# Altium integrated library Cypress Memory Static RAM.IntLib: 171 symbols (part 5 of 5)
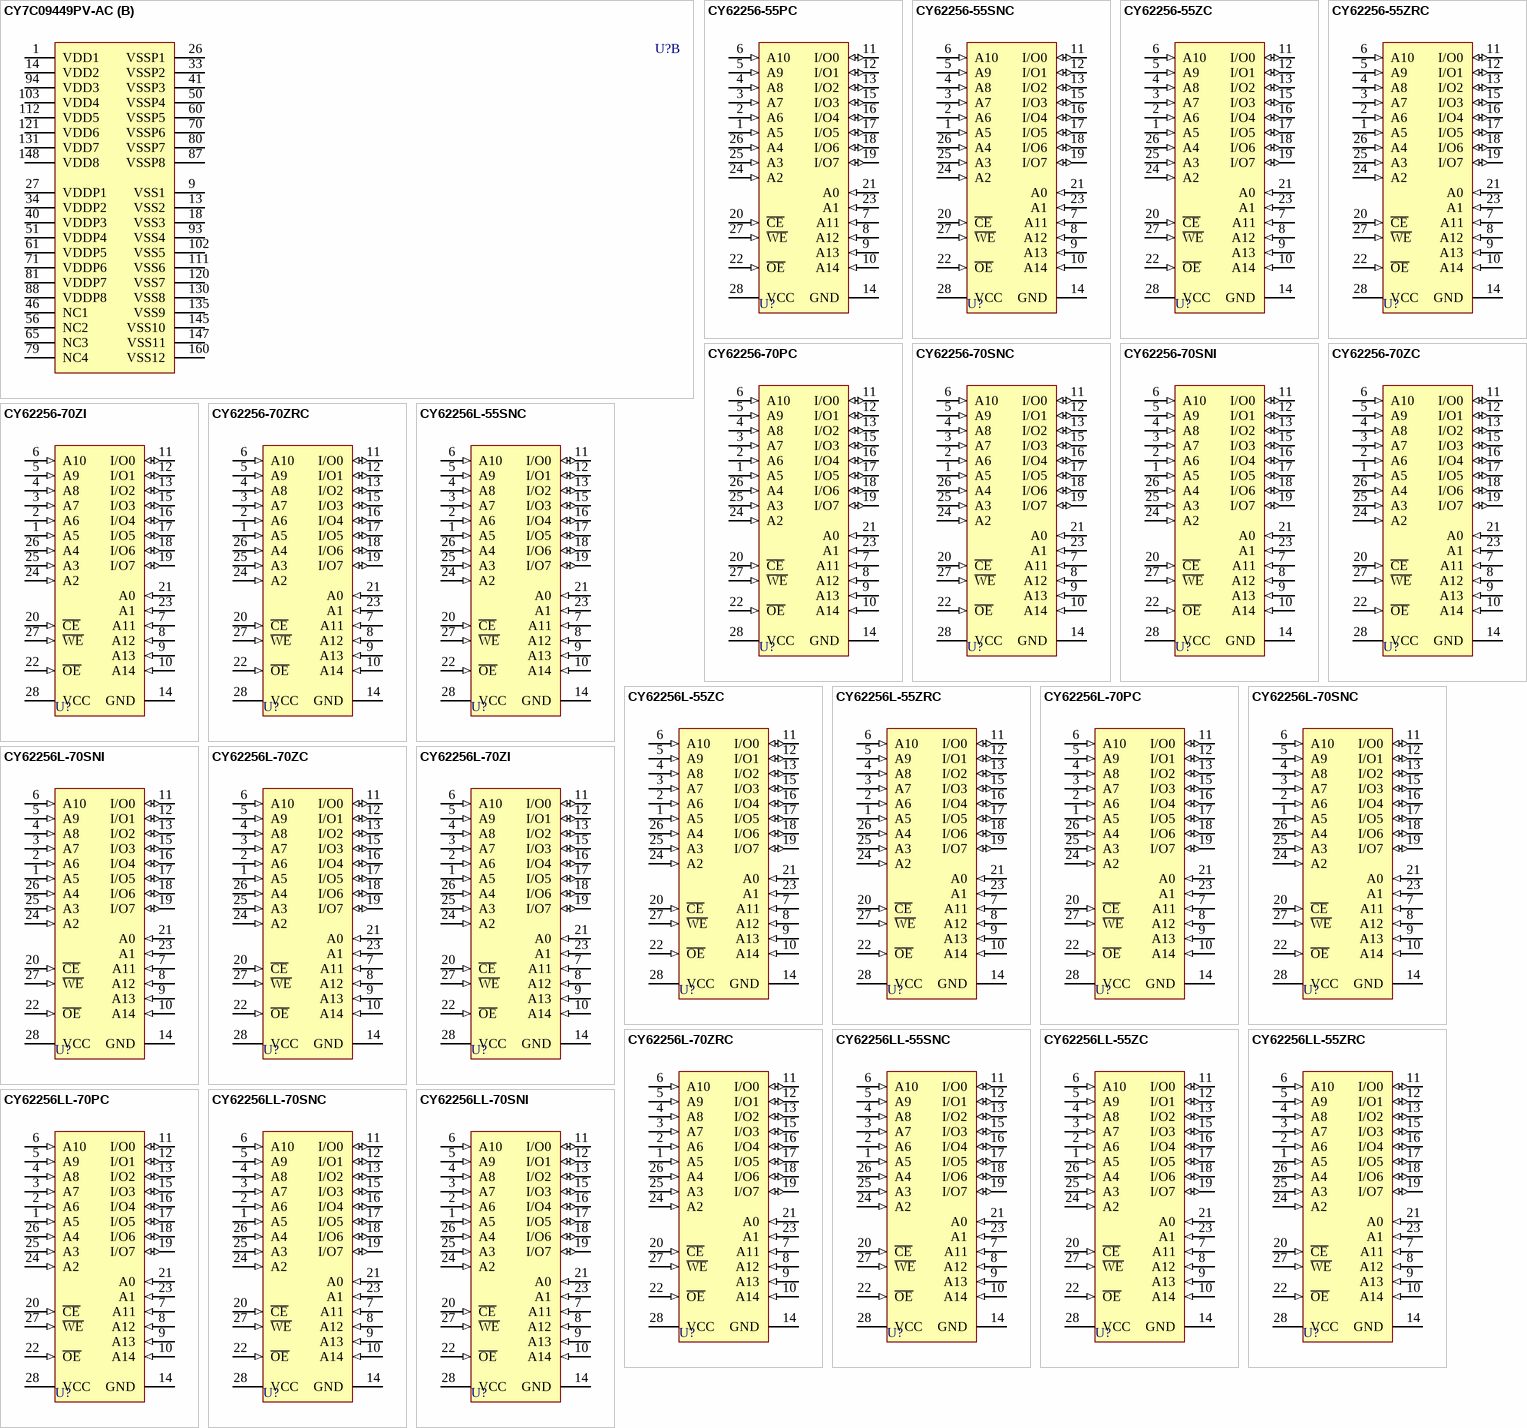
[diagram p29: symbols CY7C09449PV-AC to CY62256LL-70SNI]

## CY7C09449PV-AC
designator U?
128K Bit Dual-Port SRAM with PCI Bus Controller
footprint TQFP160_N (Thin QFP, 160-Leads, Body 24x24mm, Pitch 0.5mm, IPC Medium Density)
footprint TQFP160_L (Thin QFP, 160-Leads, Body 24x24mm, Pitch 0.5mm, IPC High Density)
footprint TQFP160_M (Thin QFP, 160-Leads, Body 24x24mm, Pitch 0.5mm, IPC Low Density)
3D model CY7C09449PV-TQFP160 (160-Pin Thin Quad Flat Pack 0.5 mm Pitch)
part A pins: 2 ADR[8] (in), 3 ADR[7] (in), 4 ADR[6] (in), 5 ADR[5] (in), 6 ADR[4] (in), 7 ADR[3] (in), 8 ADR[2] (in), 10 ALE (in), 11 ~{IRQ_IN} (in), 12 ~{IRQ_OUT} (hiz), 15 RSTOUTD (out), 16 ~{RSTOUTD} (out), 17 ~{RSTOUT} (out), 19 ~{SELECT} (in), 20 SDA (oc), 21 SCL (oc), 22 TEST_MODE (in), 23 ~{INTA} (oc), 24 ~{RST} (in), 25 CLK (in), 28 ~{GNT} (hiz), 29 ~{REQ} (hiz), 30 AD[31] (hiz), 31 AD[30] (hiz), 32 AD[29] (hiz), 35 AD[28] (hiz), 36 AD[27] (hiz), 37 AD[26] (hiz), 38 AD[25] (hiz), 39 AD[24] (hiz), 42 C/~{BE}[3] (hiz), 43 IDSEL (in), 44 AD[23] (hiz), 45 AD[22] (hiz), 47 AD[21] (hiz), 48 AD[20] (hiz), 49 AD[19] (hiz), 52 AD[18] (hiz), 53 AD[17] (hiz), 54 AD[16] (hiz), 55 C/~{BE}[2] (hiz), 57 ~{FRAME} (hiz), 58 ~{IRDY} (hiz), 59 ~{TRDY} (hiz), 62 ~{DEVSEL} (hiz), 63 ~{STOP} (hiz), 64 ~{PERR} (hiz), 66 ~{SERR} (oc), 67 PAR (hiz), 68 C/~{BE}[1] (hiz), 69 AD[15] (hiz), 72 AD[14] (hiz), 73 AD[13] (hiz), 74 AD[12] (hiz), 75 AD[11] (hiz), 76 AD[10] (hiz), 77 AD[9] (hiz), 78 AD[8] (hiz), 82 C/~{BE}[0] (hiz), 83 AD[7] (hiz), 84 AD[6] (hiz), 85 AD[5] (hiz), 86 AD[4] (hiz), 89 AD[3] (hiz), 90 AD[2] (hiz), 91 AD[1] (hiz), 92 AD[0] (hiz), 95 DQ[0] (io), 96 DQ[1] (io), 97 DQ[2] (io), 98 DQ[3] (io), 99 DQ[4] (io), 100 DQ[5] (io), 101 DQ[6] (io), 104 DQ[7] (io), 105 DQ[8] (io), 106 DQ[9] (io), 107 DQ[10] (io), 108 DQ[11] (io), 109 DQ[12] (io), 110 DQ[13] (io), 113 DQ[14] (io), 114 DQ[15] (io), 115 DQ[16] (io), 116 DQ[17] (io), 117 DQ[18] (io), 118 DQ[19] (io), 119 DQ[20] (io), 122 DQ[21] (io), 123 DQ[22] (io), 124 DQ[23] (io), 125 DQ[24] (io), 126 DQ[25] (io), 127 DQ[26] (io), 128 DQ[27] (io), 129 DQ[28] (io), 132 DQ[29] (io), 133 DQ[30] (io), 134 DQ[31] (io), 136 ~{BLAST} (in), 137 ~{READ} (in), 138 ~{WRTE} (in), 139 RDY_IN (in), 140 ~{RDY_IN} (in), 141 ~{RDY_OUT} (out), 142 PCLKOUT0 (out), 143 PCLKOUT1 (out), 144 PCLKOUT2 (out), 146 CLKIN (in), 149 ~{BE}[3] (in), 150 ~{BE}[2] (in), 151 ~{BE}[1] (in), 152 ~{BE}[0] (in), 153 ~{STROBE} (in), 154 ADR[14] (in), 155 ADR[13] (in), 156 ADR[12] (in), 157 ADR[11] (in), 158 ADR[10] (in), 159 ADR[9] (in)
part B pins: 1 VDD1 (power), 9 VSS1 (power), 13 VSS2 (power), 14 VDD2 (power), 18 VSS3 (power), 26 VSSP1 (power), 27 VDDP1 (power), 33 VSSP2 (power), 34 VDDP2 (power), 40 VDDP3 (power), 41 VSSP3 (power), 46 NC1, 50 VSSP4 (power), 51 VDDP4 (power), 56 NC2, 60 VSSP5 (power), 61 VDDP5 (power), 65 NC3, 70 VSSP6 (power), 71 VDDP6 (power), 79 NC4, 80 VSSP7 (power), 81 VDDP7 (power), 87 VSSP8 (power), 88 VDDP8 (power), 93 VSS4 (power), 94 VDD3 (power), 102 VSS5 (power), 103 VDD4 (power), 111 VSS6 (power), 112 VDD5 (power), 120 VSS7 (power), 121 VDD6 (power), 130 VSS8 (power), 131 VDD7 (power), 135 VSS9 (power), 145 VSS10 (power), 147 VSS11 (power), 148 VDD8 (power), 160 VSS12 (power)

## CY62256-55PC
designator U?
32K x 8 Static RAM
footprint P15 (DIP, Molded; 28 Leads; Row Spacing 15.24 mm; Pitch 2.54 mm)
3D model P15 (DIP, Molded; 28 Leads; Row Spacing 15.24 mm; Pitch 2.54 mm)
pins: 1 A5 (in), 2 A6 (in), 3 A7 (in), 4 A8 (in), 5 A9 (in), 6 A10 (in), 7 A11 (in), 8 A12 (in), 9 A13 (in), 10 A14 (in), 11 I/O0 (io), 12 I/O1 (io), 13 I/O2 (io), 14 GND (power), 15 I/O3 (io), 16 I/O4 (io), 17 I/O5 (io), 18 I/O6 (io), 19 I/O7 (io), 20 ~{CE} (in), 21 A0 (in), 22 ~{OE} (in), 23 A1 (in), 24 A2 (in), 25 A3 (in), 26 A4 (in), 27 ~{WE} (in), 28 VCC (power)

## CY62256-55SNC
designator U?
32K x 8 Static RAM
footprint S22_N (SOIC, 28-Leads, Body 18.4x7.5mm, Pitch 1.27mm, IPC Medium Density)
footprint S22_L (SOIC, 28-Leads, Body 18.4x7.5mm, Pitch 1.27mm, IPC High Density)
footprint S22_M (SOIC, 28-Leads, Body 18.4x7.5mm, Pitch 1.27mm, IPC Low Density)
3D model S22 (28-Pin Plastic Small Outline Integrated Circuit 1.27 mm Pitch)
pins: 1 A5 (in), 2 A6 (in), 3 A7 (in), 4 A8 (in), 5 A9 (in), 6 A10 (in), 7 A11 (in), 8 A12 (in), 9 A13 (in), 10 A14 (in), 11 I/O0 (io), 12 I/O1 (io), 13 I/O2 (io), 14 GND (power), 15 I/O3 (io), 16 I/O4 (io), 17 I/O5 (io), 18 I/O6 (io), 19 I/O7 (io), 20 ~{CE} (in), 21 A0 (in), 22 ~{OE} (in), 23 A1 (in), 24 A2 (in), 25 A3 (in), 26 A4 (in), 27 ~{WE} (in), 28 VCC (power)

## CY62256-55ZC
designator U?
32K x 8 Static RAM
footprint Z28_N (TSSOP, 28-Leads, Body 8x11.8mm, Pitch 0.55mm, Unconventional Pinout, IPC Medium Density)
footprint Z28_L (TSSOP, 28-Leads, Body 8x11.8mm, Pitch 0.55mm, Unconventional Pinout, IPC High Density)
footprint Z28_M (TSSOP, 28-Leads, Body 8x11.8mm, Pitch 0.55mm, Unconventional Pinout, IPC Low Density)
3D model Z28 (28-Pin Thin Small Outline Package Type 1 - 8 x 13.4 mm)
pins: 1 A5 (in), 2 A6 (in), 3 A7 (in), 4 A8 (in), 5 A9 (in), 6 A10 (in), 7 A11 (in), 8 A12 (in), 9 A13 (in), 10 A14 (in), 11 I/O0 (io), 12 I/O1 (io), 13 I/O2 (io), 14 GND (power), 15 I/O3 (io), 16 I/O4 (io), 17 I/O5 (io), 18 I/O6 (io), 19 I/O7 (io), 20 ~{CE} (in), 21 A0 (in), 22 ~{OE} (in), 23 A1 (in), 24 A2 (in), 25 A3 (in), 26 A4 (in), 27 ~{WE} (in), 28 VCC (power)

## CY62256-55ZRC
designator U?
32K x 8 Static RAM
footprint ZR28_N (TSSOP, 28-Leads, Body 8x11.8mm, Pitch 0.55mm, Reverse Pinning, IPC Medium Density)
footprint ZR28_L (TSSOP, 28-Leads, Body 8x11.8mm, Pitch 0.55mm, Reverse Pinning, IPC High Density)
footprint ZR28_M (TSSOP, 28-Leads, Body 8x11.8mm, Pitch 0.55mm, Reverse Pinning, IPC Low Density)
3D model Z28 (28-Pin Reverse Type 1Thin Small Outline Package - 8 x 13.4 mm)
pins: 1 A5 (in), 2 A6 (in), 3 A7 (in), 4 A8 (in), 5 A9 (in), 6 A10 (in), 7 A11 (in), 8 A12 (in), 9 A13 (in), 10 A14 (in), 11 I/O0 (io), 12 I/O1 (io), 13 I/O2 (io), 14 GND (power), 15 I/O3 (io), 16 I/O4 (io), 17 I/O5 (io), 18 I/O6 (io), 19 I/O7 (io), 20 ~{CE} (in), 21 A0 (in), 22 ~{OE} (in), 23 A1 (in), 24 A2 (in), 25 A3 (in), 26 A4 (in), 27 ~{WE} (in), 28 VCC (power)

## CY62256-70PC
designator U?
32K x 8 Static RAM
footprint P15 (DIP, Molded; 28 Leads; Row Spacing 15.24 mm; Pitch 2.54 mm)
3D model P15 (DIP, Molded; 28 Leads; Row Spacing 15.24 mm; Pitch 2.54 mm)
pins: 1 A5 (in), 2 A6 (in), 3 A7 (in), 4 A8 (in), 5 A9 (in), 6 A10 (in), 7 A11 (in), 8 A12 (in), 9 A13 (in), 10 A14 (in), 11 I/O0 (io), 12 I/O1 (io), 13 I/O2 (io), 14 GND (power), 15 I/O3 (io), 16 I/O4 (io), 17 I/O5 (io), 18 I/O6 (io), 19 I/O7 (io), 20 ~{CE} (in), 21 A0 (in), 22 ~{OE} (in), 23 A1 (in), 24 A2 (in), 25 A3 (in), 26 A4 (in), 27 ~{WE} (in), 28 VCC (power)

## CY62256-70SNC
designator U?
32K x 8 Static RAM
footprint S22_N (SOIC, 28-Leads, Body 18.4x7.5mm, Pitch 1.27mm, IPC Medium Density)
footprint S22_L (SOIC, 28-Leads, Body 18.4x7.5mm, Pitch 1.27mm, IPC High Density)
footprint S22_M (SOIC, 28-Leads, Body 18.4x7.5mm, Pitch 1.27mm, IPC Low Density)
3D model S22 (28-Pin Plastic Small Outline Integrated Circuit 1.27 mm Pitch)
pins: 1 A5 (in), 2 A6 (in), 3 A7 (in), 4 A8 (in), 5 A9 (in), 6 A10 (in), 7 A11 (in), 8 A12 (in), 9 A13 (in), 10 A14 (in), 11 I/O0 (io), 12 I/O1 (io), 13 I/O2 (io), 14 GND (power), 15 I/O3 (io), 16 I/O4 (io), 17 I/O5 (io), 18 I/O6 (io), 19 I/O7 (io), 20 ~{CE} (in), 21 A0 (in), 22 ~{OE} (in), 23 A1 (in), 24 A2 (in), 25 A3 (in), 26 A4 (in), 27 ~{WE} (in), 28 VCC (power)

## CY62256-70SNI
designator U?
32K x 8 Static RAM
footprint S22_N (SOIC, 28-Leads, Body 18.4x7.5mm, Pitch 1.27mm, IPC Medium Density)
footprint S22_L (SOIC, 28-Leads, Body 18.4x7.5mm, Pitch 1.27mm, IPC High Density)
footprint S22_M (SOIC, 28-Leads, Body 18.4x7.5mm, Pitch 1.27mm, IPC Low Density)
3D model S22 (28-Pin Plastic Small Outline Integrated Circuit 1.27 mm Pitch)
pins: 1 A5 (in), 2 A6 (in), 3 A7 (in), 4 A8 (in), 5 A9 (in), 6 A10 (in), 7 A11 (in), 8 A12 (in), 9 A13 (in), 10 A14 (in), 11 I/O0 (io), 12 I/O1 (io), 13 I/O2 (io), 14 GND (power), 15 I/O3 (io), 16 I/O4 (io), 17 I/O5 (io), 18 I/O6 (io), 19 I/O7 (io), 20 ~{CE} (in), 21 A0 (in), 22 ~{OE} (in), 23 A1 (in), 24 A2 (in), 25 A3 (in), 26 A4 (in), 27 ~{WE} (in), 28 VCC (power)

## CY62256-70ZC
designator U?
32K x 8 Static RAM
footprint Z28_N (TSSOP, 28-Leads, Body 8x11.8mm, Pitch 0.55mm, Unconventional Pinout, IPC Medium Density)
footprint Z28_L (TSSOP, 28-Leads, Body 8x11.8mm, Pitch 0.55mm, Unconventional Pinout, IPC High Density)
footprint Z28_M (TSSOP, 28-Leads, Body 8x11.8mm, Pitch 0.55mm, Unconventional Pinout, IPC Low Density)
3D model Z28 (28-Pin Thin Small Outline Package Type 1 - 8 x 13.4 mm)
pins: 1 A5 (in), 2 A6 (in), 3 A7 (in), 4 A8 (in), 5 A9 (in), 6 A10 (in), 7 A11 (in), 8 A12 (in), 9 A13 (in), 10 A14 (in), 11 I/O0 (io), 12 I/O1 (io), 13 I/O2 (io), 14 GND (power), 15 I/O3 (io), 16 I/O4 (io), 17 I/O5 (io), 18 I/O6 (io), 19 I/O7 (io), 20 ~{CE} (in), 21 A0 (in), 22 ~{OE} (in), 23 A1 (in), 24 A2 (in), 25 A3 (in), 26 A4 (in), 27 ~{WE} (in), 28 VCC (power)

## CY62256-70ZI
designator U?
32K x 8 Static RAM
footprint Z28_N (TSSOP, 28-Leads, Body 8x11.8mm, Pitch 0.55mm, Unconventional Pinout, IPC Medium Density)
footprint Z28_L (TSSOP, 28-Leads, Body 8x11.8mm, Pitch 0.55mm, Unconventional Pinout, IPC High Density)
footprint Z28_M (TSSOP, 28-Leads, Body 8x11.8mm, Pitch 0.55mm, Unconventional Pinout, IPC Low Density)
3D model Z28 (28-Pin Thin Small Outline Package Type 1 - 8 x 13.4 mm)
pins: 1 A5 (in), 2 A6 (in), 3 A7 (in), 4 A8 (in), 5 A9 (in), 6 A10 (in), 7 A11 (in), 8 A12 (in), 9 A13 (in), 10 A14 (in), 11 I/O0 (io), 12 I/O1 (io), 13 I/O2 (io), 14 GND (power), 15 I/O3 (io), 16 I/O4 (io), 17 I/O5 (io), 18 I/O6 (io), 19 I/O7 (io), 20 ~{CE} (in), 21 A0 (in), 22 ~{OE} (in), 23 A1 (in), 24 A2 (in), 25 A3 (in), 26 A4 (in), 27 ~{WE} (in), 28 VCC (power)

## CY62256-70ZRC
designator U?
32K x 8 Static RAM
footprint ZR28_N (TSSOP, 28-Leads, Body 8x11.8mm, Pitch 0.55mm, Reverse Pinning, IPC Medium Density)
footprint ZR28_L (TSSOP, 28-Leads, Body 8x11.8mm, Pitch 0.55mm, Reverse Pinning, IPC High Density)
footprint ZR28_M (TSSOP, 28-Leads, Body 8x11.8mm, Pitch 0.55mm, Reverse Pinning, IPC Low Density)
3D model Z28 (28-Pin Reverse Type 1Thin Small Outline Package - 8 x 13.4 mm)
pins: 1 A5 (in), 2 A6 (in), 3 A7 (in), 4 A8 (in), 5 A9 (in), 6 A10 (in), 7 A11 (in), 8 A12 (in), 9 A13 (in), 10 A14 (in), 11 I/O0 (io), 12 I/O1 (io), 13 I/O2 (io), 14 GND (power), 15 I/O3 (io), 16 I/O4 (io), 17 I/O5 (io), 18 I/O6 (io), 19 I/O7 (io), 20 ~{CE} (in), 21 A0 (in), 22 ~{OE} (in), 23 A1 (in), 24 A2 (in), 25 A3 (in), 26 A4 (in), 27 ~{WE} (in), 28 VCC (power)

## CY62256L-55SNC
designator U?
32K x 8 Static RAM
footprint S22_N (SOIC, 28-Leads, Body 18.4x7.5mm, Pitch 1.27mm, IPC Medium Density)
footprint S22_L (SOIC, 28-Leads, Body 18.4x7.5mm, Pitch 1.27mm, IPC High Density)
footprint S22_M (SOIC, 28-Leads, Body 18.4x7.5mm, Pitch 1.27mm, IPC Low Density)
3D model S22 (28-Pin Plastic Small Outline Integrated Circuit 1.27 mm Pitch)
pins: 1 A5 (in), 2 A6 (in), 3 A7 (in), 4 A8 (in), 5 A9 (in), 6 A10 (in), 7 A11 (in), 8 A12 (in), 9 A13 (in), 10 A14 (in), 11 I/O0 (io), 12 I/O1 (io), 13 I/O2 (io), 14 GND (power), 15 I/O3 (io), 16 I/O4 (io), 17 I/O5 (io), 18 I/O6 (io), 19 I/O7 (io), 20 ~{CE} (in), 21 A0 (in), 22 ~{OE} (in), 23 A1 (in), 24 A2 (in), 25 A3 (in), 26 A4 (in), 27 ~{WE} (in), 28 VCC (power)

## CY62256L-55ZC
designator U?
32K x 8 Static RAM
footprint Z28_N (TSSOP, 28-Leads, Body 8x11.8mm, Pitch 0.55mm, Unconventional Pinout, IPC Medium Density)
footprint Z28_L (TSSOP, 28-Leads, Body 8x11.8mm, Pitch 0.55mm, Unconventional Pinout, IPC High Density)
footprint Z28_M (TSSOP, 28-Leads, Body 8x11.8mm, Pitch 0.55mm, Unconventional Pinout, IPC Low Density)
3D model Z28 (28-Pin Thin Small Outline Package Type 1 - 8 x 13.4 mm)
pins: 1 A5 (in), 2 A6 (in), 3 A7 (in), 4 A8 (in), 5 A9 (in), 6 A10 (in), 7 A11 (in), 8 A12 (in), 9 A13 (in), 10 A14 (in), 11 I/O0 (io), 12 I/O1 (io), 13 I/O2 (io), 14 GND (power), 15 I/O3 (io), 16 I/O4 (io), 17 I/O5 (io), 18 I/O6 (io), 19 I/O7 (io), 20 ~{CE} (in), 21 A0 (in), 22 ~{OE} (in), 23 A1 (in), 24 A2 (in), 25 A3 (in), 26 A4 (in), 27 ~{WE} (in), 28 VCC (power)

## CY62256L-55ZRC
designator U?
32K x 8 Static RAM
footprint ZR28_N (TSSOP, 28-Leads, Body 8x11.8mm, Pitch 0.55mm, Reverse Pinning, IPC Medium Density)
footprint ZR28_L (TSSOP, 28-Leads, Body 8x11.8mm, Pitch 0.55mm, Reverse Pinning, IPC High Density)
footprint ZR28_M (TSSOP, 28-Leads, Body 8x11.8mm, Pitch 0.55mm, Reverse Pinning, IPC Low Density)
3D model Z28 (28-Pin Reverse Type 1Thin Small Outline Package - 8 x 13.4 mm)
pins: 1 A5 (in), 2 A6 (in), 3 A7 (in), 4 A8 (in), 5 A9 (in), 6 A10 (in), 7 A11 (in), 8 A12 (in), 9 A13 (in), 10 A14 (in), 11 I/O0 (io), 12 I/O1 (io), 13 I/O2 (io), 14 GND (power), 15 I/O3 (io), 16 I/O4 (io), 17 I/O5 (io), 18 I/O6 (io), 19 I/O7 (io), 20 ~{CE} (in), 21 A0 (in), 22 ~{OE} (in), 23 A1 (in), 24 A2 (in), 25 A3 (in), 26 A4 (in), 27 ~{WE} (in), 28 VCC (power)

## CY62256L-70PC
designator U?
32K x 8 Static RAM
footprint P15 (DIP, Molded; 28 Leads; Row Spacing 15.24 mm; Pitch 2.54 mm)
3D model P15 (DIP, Molded; 28 Leads; Row Spacing 15.24 mm; Pitch 2.54 mm)
pins: 1 A5 (in), 2 A6 (in), 3 A7 (in), 4 A8 (in), 5 A9 (in), 6 A10 (in), 7 A11 (in), 8 A12 (in), 9 A13 (in), 10 A14 (in), 11 I/O0 (io), 12 I/O1 (io), 13 I/O2 (io), 14 GND (power), 15 I/O3 (io), 16 I/O4 (io), 17 I/O5 (io), 18 I/O6 (io), 19 I/O7 (io), 20 ~{CE} (in), 21 A0 (in), 22 ~{OE} (in), 23 A1 (in), 24 A2 (in), 25 A3 (in), 26 A4 (in), 27 ~{WE} (in), 28 VCC (power)

## CY62256L-70SNC
designator U?
32K x 8 Static RAM
footprint S22_N (SOIC, 28-Leads, Body 18.4x7.5mm, Pitch 1.27mm, IPC Medium Density)
footprint S22_L (SOIC, 28-Leads, Body 18.4x7.5mm, Pitch 1.27mm, IPC High Density)
footprint S22_M (SOIC, 28-Leads, Body 18.4x7.5mm, Pitch 1.27mm, IPC Low Density)
3D model S22 (28-Pin Plastic Small Outline Integrated Circuit 1.27 mm Pitch)
pins: 1 A5 (in), 2 A6 (in), 3 A7 (in), 4 A8 (in), 5 A9 (in), 6 A10 (in), 7 A11 (in), 8 A12 (in), 9 A13 (in), 10 A14 (in), 11 I/O0 (io), 12 I/O1 (io), 13 I/O2 (io), 14 GND (power), 15 I/O3 (io), 16 I/O4 (io), 17 I/O5 (io), 18 I/O6 (io), 19 I/O7 (io), 20 ~{CE} (in), 21 A0 (in), 22 ~{OE} (in), 23 A1 (in), 24 A2 (in), 25 A3 (in), 26 A4 (in), 27 ~{WE} (in), 28 VCC (power)

## CY62256L-70SNI
designator U?
32K x 8 Static RAM
footprint S22_N (SOIC, 28-Leads, Body 18.4x7.5mm, Pitch 1.27mm, IPC Medium Density)
footprint S22_L (SOIC, 28-Leads, Body 18.4x7.5mm, Pitch 1.27mm, IPC High Density)
footprint S22_M (SOIC, 28-Leads, Body 18.4x7.5mm, Pitch 1.27mm, IPC Low Density)
3D model S22 (28-Pin Plastic Small Outline Integrated Circuit 1.27 mm Pitch)
pins: 1 A5 (in), 2 A6 (in), 3 A7 (in), 4 A8 (in), 5 A9 (in), 6 A10 (in), 7 A11 (in), 8 A12 (in), 9 A13 (in), 10 A14 (in), 11 I/O0 (io), 12 I/O1 (io), 13 I/O2 (io), 14 GND (power), 15 I/O3 (io), 16 I/O4 (io), 17 I/O5 (io), 18 I/O6 (io), 19 I/O7 (io), 20 ~{CE} (in), 21 A0 (in), 22 ~{OE} (in), 23 A1 (in), 24 A2 (in), 25 A3 (in), 26 A4 (in), 27 ~{WE} (in), 28 VCC (power)

## CY62256L-70ZC
designator U?
32K x 8 Static RAM
footprint Z28_N (TSSOP, 28-Leads, Body 8x11.8mm, Pitch 0.55mm, Unconventional Pinout, IPC Medium Density)
footprint Z28_L (TSSOP, 28-Leads, Body 8x11.8mm, Pitch 0.55mm, Unconventional Pinout, IPC High Density)
footprint Z28_M (TSSOP, 28-Leads, Body 8x11.8mm, Pitch 0.55mm, Unconventional Pinout, IPC Low Density)
3D model Z28 (28-Pin Thin Small Outline Package Type 1 - 8 x 13.4 mm)
pins: 1 A5 (in), 2 A6 (in), 3 A7 (in), 4 A8 (in), 5 A9 (in), 6 A10 (in), 7 A11 (in), 8 A12 (in), 9 A13 (in), 10 A14 (in), 11 I/O0 (io), 12 I/O1 (io), 13 I/O2 (io), 14 GND (power), 15 I/O3 (io), 16 I/O4 (io), 17 I/O5 (io), 18 I/O6 (io), 19 I/O7 (io), 20 ~{CE} (in), 21 A0 (in), 22 ~{OE} (in), 23 A1 (in), 24 A2 (in), 25 A3 (in), 26 A4 (in), 27 ~{WE} (in), 28 VCC (power)

## CY62256L-70ZI
designator U?
32K x 8 Static RAM
footprint Z28_N (TSSOP, 28-Leads, Body 8x11.8mm, Pitch 0.55mm, Unconventional Pinout, IPC Medium Density)
footprint Z28_L (TSSOP, 28-Leads, Body 8x11.8mm, Pitch 0.55mm, Unconventional Pinout, IPC High Density)
footprint Z28_M (TSSOP, 28-Leads, Body 8x11.8mm, Pitch 0.55mm, Unconventional Pinout, IPC Low Density)
3D model Z28 (28-Pin Thin Small Outline Package Type 1 - 8 x 13.4 mm)
pins: 1 A5 (in), 2 A6 (in), 3 A7 (in), 4 A8 (in), 5 A9 (in), 6 A10 (in), 7 A11 (in), 8 A12 (in), 9 A13 (in), 10 A14 (in), 11 I/O0 (io), 12 I/O1 (io), 13 I/O2 (io), 14 GND (power), 15 I/O3 (io), 16 I/O4 (io), 17 I/O5 (io), 18 I/O6 (io), 19 I/O7 (io), 20 ~{CE} (in), 21 A0 (in), 22 ~{OE} (in), 23 A1 (in), 24 A2 (in), 25 A3 (in), 26 A4 (in), 27 ~{WE} (in), 28 VCC (power)

## CY62256L-70ZRC
designator U?
32K x 8 Static RAM
footprint ZR28_N (TSSOP, 28-Leads, Body 8x11.8mm, Pitch 0.55mm, Reverse Pinning, IPC Medium Density)
footprint ZR28_L (TSSOP, 28-Leads, Body 8x11.8mm, Pitch 0.55mm, Reverse Pinning, IPC High Density)
footprint ZR28_M (TSSOP, 28-Leads, Body 8x11.8mm, Pitch 0.55mm, Reverse Pinning, IPC Low Density)
3D model Z28 (28-Pin Reverse Type 1Thin Small Outline Package - 8 x 13.4 mm)
pins: 1 A5 (in), 2 A6 (in), 3 A7 (in), 4 A8 (in), 5 A9 (in), 6 A10 (in), 7 A11 (in), 8 A12 (in), 9 A13 (in), 10 A14 (in), 11 I/O0 (io), 12 I/O1 (io), 13 I/O2 (io), 14 GND (power), 15 I/O3 (io), 16 I/O4 (io), 17 I/O5 (io), 18 I/O6 (io), 19 I/O7 (io), 20 ~{CE} (in), 21 A0 (in), 22 ~{OE} (in), 23 A1 (in), 24 A2 (in), 25 A3 (in), 26 A4 (in), 27 ~{WE} (in), 28 VCC (power)

## CY62256LL-55SNC
designator U?
32K x 8 Static RAM
footprint S22_N (SOIC, 28-Leads, Body 18.4x7.5mm, Pitch 1.27mm, IPC Medium Density)
footprint S22_L (SOIC, 28-Leads, Body 18.4x7.5mm, Pitch 1.27mm, IPC High Density)
footprint S22_M (SOIC, 28-Leads, Body 18.4x7.5mm, Pitch 1.27mm, IPC Low Density)
3D model S22 (28-Pin Plastic Small Outline Integrated Circuit 1.27 mm Pitch)
pins: 1 A5 (in), 2 A6 (in), 3 A7 (in), 4 A8 (in), 5 A9 (in), 6 A10 (in), 7 A11 (in), 8 A12 (in), 9 A13 (in), 10 A14 (in), 11 I/O0 (io), 12 I/O1 (io), 13 I/O2 (io), 14 GND (power), 15 I/O3 (io), 16 I/O4 (io), 17 I/O5 (io), 18 I/O6 (io), 19 I/O7 (io), 20 ~{CE} (in), 21 A0 (in), 22 ~{OE} (in), 23 A1 (in), 24 A2 (in), 25 A3 (in), 26 A4 (in), 27 ~{WE} (in), 28 VCC (power)

## CY62256LL-55ZC
designator U?
32K x 8 Static RAM
footprint Z28_N (TSSOP, 28-Leads, Body 8x11.8mm, Pitch 0.55mm, Unconventional Pinout, IPC Medium Density)
footprint Z28_L (TSSOP, 28-Leads, Body 8x11.8mm, Pitch 0.55mm, Unconventional Pinout, IPC High Density)
footprint Z28_M (TSSOP, 28-Leads, Body 8x11.8mm, Pitch 0.55mm, Unconventional Pinout, IPC Low Density)
3D model Z28 (28-Pin Thin Small Outline Package Type 1 - 8 x 13.4 mm)
pins: 1 A5 (in), 2 A6 (in), 3 A7 (in), 4 A8 (in), 5 A9 (in), 6 A10 (in), 7 A11 (in), 8 A12 (in), 9 A13 (in), 10 A14 (in), 11 I/O0 (io), 12 I/O1 (io), 13 I/O2 (io), 14 GND (power), 15 I/O3 (io), 16 I/O4 (io), 17 I/O5 (io), 18 I/O6 (io), 19 I/O7 (io), 20 ~{CE} (in), 21 A0 (in), 22 ~{OE} (in), 23 A1 (in), 24 A2 (in), 25 A3 (in), 26 A4 (in), 27 ~{WE} (in), 28 VCC (power)

## CY62256LL-55ZRC
designator U?
32K x 8 Static RAM
footprint ZR28_N (TSSOP, 28-Leads, Body 8x11.8mm, Pitch 0.55mm, Reverse Pinning, IPC Medium Density)
footprint ZR28_L (TSSOP, 28-Leads, Body 8x11.8mm, Pitch 0.55mm, Reverse Pinning, IPC High Density)
footprint ZR28_M (TSSOP, 28-Leads, Body 8x11.8mm, Pitch 0.55mm, Reverse Pinning, IPC Low Density)
3D model Z28 (28-Pin Reverse Type 1Thin Small Outline Package - 8 x 13.4 mm)
pins: 1 A5 (in), 2 A6 (in), 3 A7 (in), 4 A8 (in), 5 A9 (in), 6 A10 (in), 7 A11 (in), 8 A12 (in), 9 A13 (in), 10 A14 (in), 11 I/O0 (io), 12 I/O1 (io), 13 I/O2 (io), 14 GND (power), 15 I/O3 (io), 16 I/O4 (io), 17 I/O5 (io), 18 I/O6 (io), 19 I/O7 (io), 20 ~{CE} (in), 21 A0 (in), 22 ~{OE} (in), 23 A1 (in), 24 A2 (in), 25 A3 (in), 26 A4 (in), 27 ~{WE} (in), 28 VCC (power)

## CY62256LL-70PC
designator U?
32K x 8 Static RAM
footprint P15 (DIP, Molded; 28 Leads; Row Spacing 15.24 mm; Pitch 2.54 mm)
3D model P15 (DIP, Molded; 28 Leads; Row Spacing 15.24 mm; Pitch 2.54 mm)
pins: 1 A5 (in), 2 A6 (in), 3 A7 (in), 4 A8 (in), 5 A9 (in), 6 A10 (in), 7 A11 (in), 8 A12 (in), 9 A13 (in), 10 A14 (in), 11 I/O0 (io), 12 I/O1 (io), 13 I/O2 (io), 14 GND (power), 15 I/O3 (io), 16 I/O4 (io), 17 I/O5 (io), 18 I/O6 (io), 19 I/O7 (io), 20 ~{CE} (in), 21 A0 (in), 22 ~{OE} (in), 23 A1 (in), 24 A2 (in), 25 A3 (in), 26 A4 (in), 27 ~{WE} (in), 28 VCC (power)

## CY62256LL-70SNC
designator U?
32K x 8 Static RAM
footprint S22_N (SOIC, 28-Leads, Body 18.4x7.5mm, Pitch 1.27mm, IPC Medium Density)
footprint S22_L (SOIC, 28-Leads, Body 18.4x7.5mm, Pitch 1.27mm, IPC High Density)
footprint S22_M (SOIC, 28-Leads, Body 18.4x7.5mm, Pitch 1.27mm, IPC Low Density)
3D model S22 (28-Pin Plastic Small Outline Integrated Circuit 1.27 mm Pitch)
pins: 1 A5 (in), 2 A6 (in), 3 A7 (in), 4 A8 (in), 5 A9 (in), 6 A10 (in), 7 A11 (in), 8 A12 (in), 9 A13 (in), 10 A14 (in), 11 I/O0 (io), 12 I/O1 (io), 13 I/O2 (io), 14 GND (power), 15 I/O3 (io), 16 I/O4 (io), 17 I/O5 (io), 18 I/O6 (io), 19 I/O7 (io), 20 ~{CE} (in), 21 A0 (in), 22 ~{OE} (in), 23 A1 (in), 24 A2 (in), 25 A3 (in), 26 A4 (in), 27 ~{WE} (in), 28 VCC (power)

## CY62256LL-70SNI
designator U?
32K x 8 Static RAM
footprint S22_N (SOIC, 28-Leads, Body 18.4x7.5mm, Pitch 1.27mm, IPC Medium Density)
footprint S22_L (SOIC, 28-Leads, Body 18.4x7.5mm, Pitch 1.27mm, IPC High Density)
footprint S22_M (SOIC, 28-Leads, Body 18.4x7.5mm, Pitch 1.27mm, IPC Low Density)
3D model S22 (28-Pin Plastic Small Outline Integrated Circuit 1.27 mm Pitch)
pins: 1 A5 (in), 2 A6 (in), 3 A7 (in), 4 A8 (in), 5 A9 (in), 6 A10 (in), 7 A11 (in), 8 A12 (in), 9 A13 (in), 10 A14 (in), 11 I/O0 (io), 12 I/O1 (io), 13 I/O2 (io), 14 GND (power), 15 I/O3 (io), 16 I/O4 (io), 17 I/O5 (io), 18 I/O6 (io), 19 I/O7 (io), 20 ~{CE} (in), 21 A0 (in), 22 ~{OE} (in), 23 A1 (in), 24 A2 (in), 25 A3 (in), 26 A4 (in), 27 ~{WE} (in), 28 VCC (power)

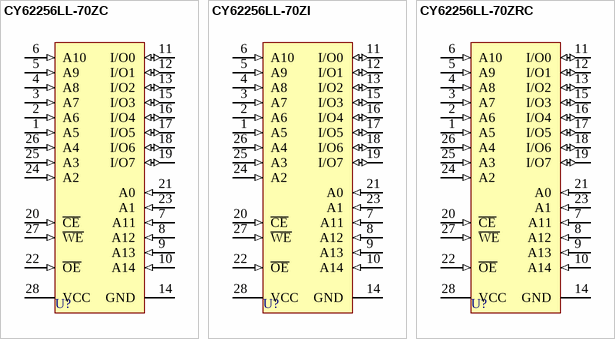
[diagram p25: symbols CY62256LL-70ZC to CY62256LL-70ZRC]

## CY62256LL-70ZC
designator U?
32K x 8 Static RAM
footprint Z28_N (TSSOP, 28-Leads, Body 8x11.8mm, Pitch 0.55mm, Unconventional Pinout, IPC Medium Density)
footprint Z28_L (TSSOP, 28-Leads, Body 8x11.8mm, Pitch 0.55mm, Unconventional Pinout, IPC High Density)
footprint Z28_M (TSSOP, 28-Leads, Body 8x11.8mm, Pitch 0.55mm, Unconventional Pinout, IPC Low Density)
3D model Z28 (28-Pin Thin Small Outline Package Type 1 - 8 x 13.4 mm)
pins: 1 A5 (in), 2 A6 (in), 3 A7 (in), 4 A8 (in), 5 A9 (in), 6 A10 (in), 7 A11 (in), 8 A12 (in), 9 A13 (in), 10 A14 (in), 11 I/O0 (io), 12 I/O1 (io), 13 I/O2 (io), 14 GND (power), 15 I/O3 (io), 16 I/O4 (io), 17 I/O5 (io), 18 I/O6 (io), 19 I/O7 (io), 20 ~{CE} (in), 21 A0 (in), 22 ~{OE} (in), 23 A1 (in), 24 A2 (in), 25 A3 (in), 26 A4 (in), 27 ~{WE} (in), 28 VCC (power)

## CY62256LL-70ZI
designator U?
32K x 8 Static RAM
footprint Z28_N (TSSOP, 28-Leads, Body 8x11.8mm, Pitch 0.55mm, Unconventional Pinout, IPC Medium Density)
footprint Z28_L (TSSOP, 28-Leads, Body 8x11.8mm, Pitch 0.55mm, Unconventional Pinout, IPC High Density)
footprint Z28_M (TSSOP, 28-Leads, Body 8x11.8mm, Pitch 0.55mm, Unconventional Pinout, IPC Low Density)
3D model Z28 (28-Pin Thin Small Outline Package Type 1 - 8 x 13.4 mm)
pins: 1 A5 (in), 2 A6 (in), 3 A7 (in), 4 A8 (in), 5 A9 (in), 6 A10 (in), 7 A11 (in), 8 A12 (in), 9 A13 (in), 10 A14 (in), 11 I/O0 (io), 12 I/O1 (io), 13 I/O2 (io), 14 GND (power), 15 I/O3 (io), 16 I/O4 (io), 17 I/O5 (io), 18 I/O6 (io), 19 I/O7 (io), 20 ~{CE} (in), 21 A0 (in), 22 ~{OE} (in), 23 A1 (in), 24 A2 (in), 25 A3 (in), 26 A4 (in), 27 ~{WE} (in), 28 VCC (power)

## CY62256LL-70ZRC
designator U?
32K x 8 Static RAM
footprint ZR28_N (TSSOP, 28-Leads, Body 8x11.8mm, Pitch 0.55mm, Reverse Pinning, IPC Medium Density)
footprint ZR28_L (TSSOP, 28-Leads, Body 8x11.8mm, Pitch 0.55mm, Reverse Pinning, IPC High Density)
footprint ZR28_M (TSSOP, 28-Leads, Body 8x11.8mm, Pitch 0.55mm, Reverse Pinning, IPC Low Density)
3D model Z28 (28-Pin Reverse Type 1Thin Small Outline Package - 8 x 13.4 mm)
pins: 1 A5 (in), 2 A6 (in), 3 A7 (in), 4 A8 (in), 5 A9 (in), 6 A10 (in), 7 A11 (in), 8 A12 (in), 9 A13 (in), 10 A14 (in), 11 I/O0 (io), 12 I/O1 (io), 13 I/O2 (io), 14 GND (power), 15 I/O3 (io), 16 I/O4 (io), 17 I/O5 (io), 18 I/O6 (io), 19 I/O7 (io), 20 ~{CE} (in), 21 A0 (in), 22 ~{OE} (in), 23 A1 (in), 24 A2 (in), 25 A3 (in), 26 A4 (in), 27 ~{WE} (in), 28 VCC (power)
